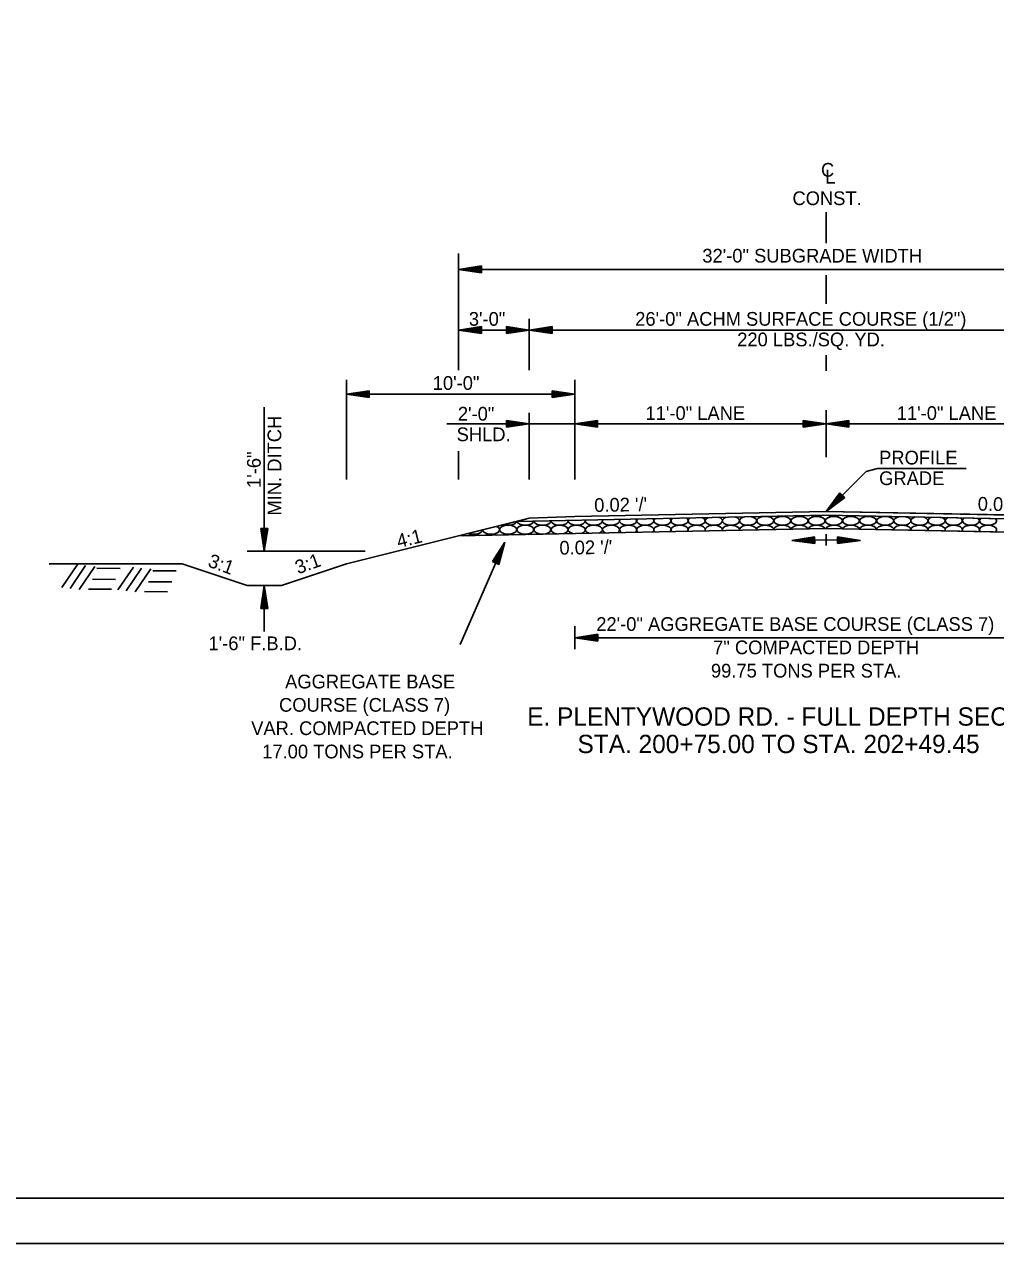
# Model space of a CAD drawing. Extents: x 1371763 to 1372860, y 385599 to 385872.
# Drawn here: x 1372733.4 to 1372775.9, y 385598.6 to 385651.9 of the extents above; entities that cross this region are included whole.
import ezdxf

# ---------------------------------------------------------------- set-up
doc = ezdxf.new("R2010")
doc.units = 0
for name, color, linetype in [('R_Border', 7, 'Continuous'), ('R_Draft', 7, 'Continuous'), ('R_Fin Surface', 7, 'Continuous'), ('R_No Plot', 7, 'Continuous')]:
    doc.layers.add(name, color=color, linetype=linetype)

msp = doc.modelspace()

# ---------------------------------------------------------------- linework, layer by layer
at = {"layer": 'R_Border'}
msp.add_line((1372857.298, 385600.577), (1372699.208, 385600.577), dxfattribs=at)
at = {"layer": 'R_Draft'}
for p, q in [((1372768.462, 385642.351), (1372768.462, 385643.701)), ((1372752.376, 385636.792), (1372752.376, 385641.892)), ((1372753.376, 385641.351), (1372752.376, 385641.201)), ((1372753.376, 385641.326), (1372752.543, 385641.201)), ((1372753.376, 385641.351), (1372753.376, 385641.051)), ((1372752.376, 385641.201), (1372784.541, 385641.201)), ((1372753.376, 385641.051), (1372752.376, 385641.201)), ((1372753.376, 385641.076), (1372752.543, 385641.201)), ((1372753.376, 385641.301), (1372752.715, 385641.201)), ((1372753.376, 385641.102), (1372752.715, 385641.201)), ((1372753.376, 385641.276), (1372752.882, 385641.201)), ((1372753.376, 385641.127), (1372752.882, 385641.201)), ((1372753.376, 385641.25), (1372753.051, 385641.201)), ((1372753.376, 385641.152), (1372753.051, 385641.201)), ((1372753.376, 385641.225), (1372753.218, 385641.201)), ((1372753.376, 385641.178), (1372753.218, 385641.201)), ((1372768.462, 385639.701), (1372768.462, 385640.951)), ((1372753.376, 385638.699), (1372752.376, 385638.549)), ((1372753.376, 385638.674), (1372752.543, 385638.549)), ((1372753.376, 385638.649), (1372752.715, 385638.549)), ((1372753.376, 385638.399), (1372753.376, 385638.699)), ((1372754.463, 385638.699), (1372755.463, 385638.549)), ((1372754.463, 385638.399), (1372754.463, 385638.699)), ((1372754.463, 385638.674), (1372755.296, 385638.549)), ((1372754.463, 385638.649), (1372755.124, 385638.549)), ((1372755.463, 385636.792), (1372755.463, 385639.037)), ((1372756.463, 385638.699), (1372755.463, 385638.549)), ((1372756.463, 385638.674), (1372755.63, 385638.549)), ((1372756.463, 385638.649), (1372755.802, 385638.549)), ((1372756.463, 385638.699), (1372756.463, 385638.399)), ((1372753.376, 385638.399), (1372752.376, 385638.549)), ((1372752.376, 385638.549), (1372755.463, 385638.549)), ((1372753.376, 385638.424), (1372752.543, 385638.549)), ((1372753.376, 385638.45), (1372752.715, 385638.549)), ((1372753.376, 385638.624), (1372752.882, 385638.549)), ((1372753.376, 385638.475), (1372752.882, 385638.549)), ((1372753.376, 385638.598), (1372753.051, 385638.549)), ((1372753.376, 385638.501), (1372753.051, 385638.549)), ((1372753.376, 385638.573), (1372753.218, 385638.549)), ((1372753.376, 385638.526), (1372753.218, 385638.549)), ((1372754.463, 385638.624), (1372754.958, 385638.549)), ((1372754.463, 385638.598), (1372754.788, 385638.549)), ((1372754.463, 385638.573), (1372754.621, 385638.549)), ((1372754.463, 385638.399), (1372755.463, 385638.549)), ((1372754.463, 385638.501), (1372754.788, 385638.549)), ((1372754.463, 385638.45), (1372755.124, 385638.549)), ((1372754.463, 385638.424), (1372755.296, 385638.549)), ((1372754.463, 385638.475), (1372754.958, 385638.549)), ((1372754.463, 385638.526), (1372754.621, 385638.549)), ((1372756.463, 385638.399), (1372755.463, 385638.549)), ((1372755.463, 385638.549), (1372781.46, 385638.549)), ((1372756.463, 385638.424), (1372755.63, 385638.549)), ((1372756.463, 385638.45), (1372755.802, 385638.549)), ((1372756.463, 385638.624), (1372755.969, 385638.549)), ((1372756.463, 385638.475), (1372755.969, 385638.549)), ((1372756.463, 385638.598), (1372756.138, 385638.549)), ((1372756.463, 385638.5), (1372756.138, 385638.549)), ((1372756.463, 385638.573), (1372756.305, 385638.549)), ((1372756.463, 385638.526), (1372756.305, 385638.549)), ((1372768.458, 385636.764), (1372768.458, 385637.449)), ((1372747.462, 385632.006), (1372747.462, 385636.371)), ((1372757.462, 385632.006), (1372757.462, 385636.371)), ((1372748.462, 385635.896), (1372747.462, 385635.746)), ((1372748.462, 385635.596), (1372747.462, 385635.746)), ((1372747.462, 385635.746), (1372757.462, 385635.746)), ((1372748.462, 385635.871), (1372747.629, 385635.746)), ((1372748.462, 385635.621), (1372747.629, 385635.746)), ((1372748.462, 385635.846), (1372747.801, 385635.746)), ((1372748.462, 385635.647), (1372747.801, 385635.746)), ((1372748.462, 385635.821), (1372747.967, 385635.746)), ((1372748.462, 385635.672), (1372747.967, 385635.746)), ((1372748.462, 385635.795), (1372748.137, 385635.746)), ((1372748.462, 385635.698), (1372748.137, 385635.746)), ((1372748.462, 385635.77), (1372748.304, 385635.746)), ((1372748.462, 385635.723), (1372748.304, 385635.746)), ((1372748.462, 385635.596), (1372748.462, 385635.896)), ((1372756.462, 385635.896), (1372757.462, 385635.746)), ((1372756.462, 385635.596), (1372756.462, 385635.896)), ((1372756.462, 385635.871), (1372757.295, 385635.746)), ((1372756.462, 385635.846), (1372757.123, 385635.746)), ((1372756.462, 385635.821), (1372756.956, 385635.746)), ((1372756.462, 385635.795), (1372756.787, 385635.746)), ((1372756.462, 385635.77), (1372756.62, 385635.746)), ((1372756.462, 385635.596), (1372757.462, 385635.746)), ((1372756.462, 385635.698), (1372756.787, 385635.746)), ((1372756.462, 385635.647), (1372757.123, 385635.746)), ((1372756.462, 385635.621), (1372757.295, 385635.746)), ((1372756.462, 385635.672), (1372756.956, 385635.746)), ((1372756.462, 385635.723), (1372756.62, 385635.746)), ((1372743.867, 385628.871), (1372743.867, 385635.169)), ((1372755.463, 385632.006), (1372755.463, 385634.933)), ((1372768.458, 385632.991), (1372768.458, 385635.045)), ((1372751.858, 385634.445), (1372768.458, 385634.445)), ((1372754.463, 385634.595), (1372755.463, 385634.445)), ((1372754.463, 385634.295), (1372754.463, 385634.595)), ((1372754.463, 385634.57), (1372755.296, 385634.445)), ((1372754.463, 385634.544), (1372755.124, 385634.445)), ((1372754.463, 385634.519), (1372754.958, 385634.445)), ((1372754.463, 385634.494), (1372754.788, 385634.445)), ((1372754.463, 385634.468), (1372754.621, 385634.445)), ((1372754.463, 385634.295), (1372755.463, 385634.445)), ((1372754.463, 385634.396), (1372754.788, 385634.445)), ((1372754.463, 385634.345), (1372755.124, 385634.445)), ((1372754.463, 385634.32), (1372755.296, 385634.445)), ((1372754.463, 385634.37), (1372754.958, 385634.445)), ((1372754.463, 385634.421), (1372754.621, 385634.445)), ((1372758.458, 385634.595), (1372757.458, 385634.445)), ((1372758.458, 385634.295), (1372757.458, 385634.445)), ((1372758.458, 385634.57), (1372757.625, 385634.445)), ((1372758.458, 385634.32), (1372757.625, 385634.445)), ((1372758.458, 385634.544), (1372757.797, 385634.445)), ((1372758.458, 385634.345), (1372757.797, 385634.445)), ((1372758.458, 385634.519), (1372757.964, 385634.445)), ((1372758.458, 385634.37), (1372757.964, 385634.445)), ((1372758.458, 385634.494), (1372758.133, 385634.445)), ((1372758.458, 385634.396), (1372758.133, 385634.445)), ((1372758.458, 385634.468), (1372758.3, 385634.445)), ((1372758.458, 385634.421), (1372758.3, 385634.445)), ((1372758.458, 385634.295), (1372758.458, 385634.595)), ((1372767.458, 385634.595), (1372768.458, 385634.445)), ((1372767.458, 385634.295), (1372767.458, 385634.595)), ((1372767.458, 385634.57), (1372768.291, 385634.445)), ((1372767.458, 385634.544), (1372768.119, 385634.445)), ((1372767.458, 385634.519), (1372767.953, 385634.445)), ((1372767.458, 385634.494), (1372767.783, 385634.445)), ((1372767.458, 385634.468), (1372767.616, 385634.445)), ((1372767.458, 385634.295), (1372768.458, 385634.445)), ((1372767.458, 385634.396), (1372767.783, 385634.445)), ((1372767.458, 385634.345), (1372768.119, 385634.445)), ((1372767.458, 385634.32), (1372768.291, 385634.445)), ((1372767.458, 385634.37), (1372767.953, 385634.445)), ((1372767.458, 385634.421), (1372767.616, 385634.445)), ((1372769.458, 385634.595), (1372768.458, 385634.445)), ((1372769.458, 385634.295), (1372768.458, 385634.445)), ((1372768.458, 385634.445), (1372786.722, 385634.445)), ((1372769.458, 385634.57), (1372768.625, 385634.445)), ((1372769.458, 385634.32), (1372768.625, 385634.445)), ((1372769.458, 385634.544), (1372768.797, 385634.445)), ((1372769.458, 385634.345), (1372768.797, 385634.445)), ((1372769.458, 385634.519), (1372768.964, 385634.445)), ((1372769.458, 385634.37), (1372768.964, 385634.445)), ((1372769.458, 385634.494), (1372769.133, 385634.445)), ((1372769.458, 385634.396), (1372769.133, 385634.445)), ((1372769.458, 385634.468), (1372769.3, 385634.445)), ((1372769.458, 385634.421), (1372769.3, 385634.445)), ((1372769.458, 385634.295), (1372769.458, 385634.595)), ((1372752.376, 385632.006), (1372752.376, 385633.256)), ((1372768.462, 385630.618), (1372770.212, 385632.368)), ((1372770.212, 385632.368), (1372770.712, 385632.493)), ((1372770.712, 385632.493), (1372774.597, 385632.493)), ((1372769.063, 385631.431), (1372768.462, 385630.618)), ((1372769.275, 385631.219), (1372768.462, 385630.618)), ((1372769.081, 385631.413), (1372768.58, 385630.736)), ((1372769.257, 385631.236), (1372768.58, 385630.736)), ((1372769.099, 385631.395), (1372768.702, 385630.857)), ((1372769.239, 385631.255), (1372768.702, 385630.857)), ((1372769.116, 385631.378), (1372768.819, 385630.975)), ((1372769.222, 385631.272), (1372768.819, 385630.975)), ((1372769.134, 385631.36), (1372768.939, 385631.095)), ((1372769.203, 385631.291), (1372768.939, 385631.095)), ((1372769.152, 385631.341), (1372769.057, 385631.213)), ((1372769.186, 385631.308), (1372769.057, 385631.213)), ((1372769.275, 385631.219), (1372769.063, 385631.431)), ((1372755.463, 385630.318), (1372747.463, 385628.318)), ((1372768.462, 385630.451), (1372754.912, 385630.18)), ((1372754.912, 385630.18), (1372768.462, 385630.451)), ((1372757.462, 385630.398), (1372755.463, 385630.318)), ((1372768.462, 385630.618), (1372757.462, 385630.398)), ((1372768.462, 385630.618), (1372757.462, 385630.398)), ((1372768.462, 385630.618), (1372779.462, 385630.398)), ((1372768.462, 385630.451), (1372782.011, 385630.18)), ((1372743.717, 385629.871), (1372743.867, 385628.871)), ((1372744.017, 385629.871), (1372743.717, 385629.871)), ((1372743.742, 385629.871), (1372743.867, 385629.038)), ((1372743.768, 385629.871), (1372743.867, 385629.21)), ((1372743.793, 385629.871), (1372743.867, 385629.376)), ((1372743.818, 385629.871), (1372743.867, 385629.546)), ((1372743.844, 385629.871), (1372743.867, 385629.713)), ((1372744.017, 385629.871), (1372743.867, 385628.871)), ((1372743.916, 385629.871), (1372743.867, 385629.546)), ((1372743.967, 385629.871), (1372743.867, 385629.21)), ((1372743.992, 385629.871), (1372743.867, 385629.038)), ((1372743.942, 385629.871), (1372743.867, 385629.376)), ((1372743.891, 385629.871), (1372743.867, 385629.713)), ((1372768.462, 385629.868), (1372752.376, 385629.546)), ((1372768.462, 385629.868), (1372784.547, 385629.546)), ((1372768.462, 385629.118), (1372768.462, 385629.618)), ((1372754.401, 385629.274), (1372752.435, 385624.797)), ((1372753.862, 385628.419), (1372754.401, 385629.274)), ((1372753.885, 385628.409), (1372754.334, 385629.121)), ((1372754.113, 385628.308), (1372754.334, 385629.121)), ((1372754.136, 385628.298), (1372754.401, 385629.274)), ((1372767.959, 385629.508), (1372766.962, 385629.338)), ((1372766.962, 385629.338), (1372768.462, 385629.368)), ((1372767.965, 385629.208), (1372766.962, 385629.338)), ((1372767.959, 385629.483), (1372767.129, 385629.341)), ((1372767.964, 385629.233), (1372767.129, 385629.341)), ((1372767.96, 385629.457), (1372767.301, 385629.345)), ((1372767.964, 385629.258), (1372767.301, 385629.345)), ((1372767.96, 385629.432), (1372767.468, 385629.348)), ((1372767.963, 385629.283), (1372767.468, 385629.348)), ((1372767.961, 385629.407), (1372767.637, 385629.351)), ((1372767.963, 385629.309), (1372767.637, 385629.351)), ((1372767.961, 385629.381), (1372767.804, 385629.355)), ((1372767.962, 385629.334), (1372767.804, 385629.355)), ((1372767.965, 385629.208), (1372767.959, 385629.508)), ((1372769.962, 385629.338), (1372768.462, 385629.368)), ((1372768.959, 385629.208), (1372768.965, 385629.508)), ((1372768.959, 385629.233), (1372769.795, 385629.341)), ((1372768.959, 385629.208), (1372769.962, 385629.338)), ((1372768.96, 385629.283), (1372769.456, 385629.348)), ((1372768.96, 385629.258), (1372769.623, 385629.345)), ((1372768.961, 385629.334), (1372769.12, 385629.355)), ((1372768.961, 385629.309), (1372769.287, 385629.351)), ((1372768.962, 385629.381), (1372769.12, 385629.355)), ((1372768.963, 385629.432), (1372769.456, 385629.348)), ((1372768.963, 385629.407), (1372769.287, 385629.351)), ((1372768.964, 385629.483), (1372769.795, 385629.341)), ((1372768.964, 385629.457), (1372769.623, 385629.345)), ((1372768.965, 385629.508), (1372769.962, 385629.338)), ((1372743.117, 385628.871), (1372748.277, 385628.871)), ((1372753.908, 385628.398), (1372754.265, 385628.964)), ((1372753.931, 385628.388), (1372754.198, 385628.811)), ((1372753.954, 385628.378), (1372754.13, 385628.656)), ((1372754.043, 385628.339), (1372754.13, 385628.656)), ((1372754.067, 385628.329), (1372754.198, 385628.811)), ((1372754.09, 385628.318), (1372754.265, 385628.964)), ((1372735.007, 385627.287), (1372735.683, 385628.288)), ((1372735.366, 385627.245), (1372736.042, 385628.247)), ((1372735.766, 385627.203), (1372736.442, 385628.205)), ((1372736.542, 385628.13), (1372737.56, 385628.121)), ((1372737.46, 385627.178), (1372738.136, 385628.18)), ((1372737.819, 385627.137), (1372738.494, 385628.138)), ((1372738.219, 385627.095), (1372738.895, 385628.096)), ((1372738.995, 385628.021), (1372740.013, 385628.013)), ((1372754.136, 385628.298), (1372753.862, 385628.419)), ((1372753.977, 385628.368), (1372754.063, 385628.503)), ((1372754.021, 385628.349), (1372754.063, 385628.503)), ((1372736.342, 385627.646), (1372737.36, 385627.637)), ((1372738.795, 385627.537), (1372739.813, 385627.529)), ((1372736.167, 385627.22), (1372737.185, 385627.212)), ((1372738.619, 385627.112), (1372739.637, 385627.103)), ((1372744.617, 385627.369), (1372743.117, 385627.369)), ((1372743.717, 385626.369), (1372743.867, 385627.369)), ((1372743.742, 385626.369), (1372743.867, 385627.202)), ((1372743.768, 385626.369), (1372743.867, 385627.03)), ((1372744.017, 385626.369), (1372743.867, 385627.369)), ((1372743.867, 385625.369), (1372743.867, 385627.369)), ((1372743.992, 385626.369), (1372743.867, 385627.202)), ((1372743.967, 385626.369), (1372743.867, 385627.03)), ((1372743.793, 385626.369), (1372743.867, 385626.864)), ((1372743.819, 385626.369), (1372743.867, 385626.694)), ((1372743.844, 385626.369), (1372743.867, 385626.527)), ((1372743.942, 385626.369), (1372743.867, 385626.864)), ((1372743.916, 385626.369), (1372743.867, 385626.694)), ((1372743.891, 385626.369), (1372743.867, 385626.527)), ((1372743.717, 385626.369), (1372744.017, 385626.369)), ((1372757.462, 385624.592), (1372757.462, 385625.592)), ((1372758.462, 385625.242), (1372757.462, 385625.092)), ((1372758.462, 385624.942), (1372757.462, 385625.092)), ((1372757.462, 385625.092), (1372779.462, 385625.092)), ((1372758.462, 385625.217), (1372757.629, 385625.092)), ((1372758.462, 385624.967), (1372757.629, 385625.092)), ((1372758.462, 385625.191), (1372757.801, 385625.092)), ((1372758.462, 385624.992), (1372757.801, 385625.092)), ((1372758.462, 385625.166), (1372757.967, 385625.092)), ((1372758.462, 385625.017), (1372757.967, 385625.092)), ((1372758.462, 385625.14), (1372758.137, 385625.092)), ((1372758.462, 385625.043), (1372758.137, 385625.092)), ((1372758.462, 385625.115), (1372758.304, 385625.092)), ((1372758.462, 385625.068), (1372758.304, 385625.092)), ((1372758.462, 385625.242), (1372758.462, 385624.942))]:
    msp.add_line(p, q, dxfattribs=at)
for points in [[(1372754.912, 385630.18), (1372752.376, 385629.546), (1372768.462, 385629.868), (1372784.547, 385629.546), (1372782.011, 385630.18), (1372768.462, 385630.451)], [(1372754.912, 385630.18), (1372755.463, 385630.318), (1372757.462, 385630.398), (1372768.462, 385630.618), (1372779.462, 385630.398), (1372781.46, 385630.318), (1372782.011, 385630.18), (1372768.462, 385630.451)]]:
    msp.add_lwpolyline(points, close=True, dxfattribs=at)
for points in [[(1372757.462, 385630.398), (1372755.463, 385630.318), (1372754.912, 385630.18)], [(1372768.462, 385630.451), (1372782.011, 385630.18), (1372781.46, 385630.318), (1372779.462, 385630.398), (1372768.462, 385630.618)]]:
    msp.add_lwpolyline(points, dxfattribs=at)
for centre, start_param, end_param in [((1372754.543, 385630.204), 4.15835, 6.162011), ((1372755.293, 385630.204), 3.26162, 6.240356), ((1372756.043, 385630.204), 3.184351, 6.317625), ((1372756.793, 385630.204), 3.107107, 6.394869), ((1372757.544, 385630.204), 3.029422, 6.472554), ((1372758.294, 385630.204), 2.950808, 6.551169), ((1372759.044, 385630.204), 2.870719, 6.631258), ((1372759.794, 385630.204), 2.788518, 6.713458), ((1372760.545, 385630.204), 2.703418, 6.798558), ((1372761.295, 385630.204), 2.614389, 6.887588), ((1372762.045, 385630.204), 2.519994, 6.981982), ((1372762.795, 385630.204), 2.418078, 7.083898), ((1372763.546, 385630.204), 2.305055, 7.196921), ((1372764.296, 385630.204), 2.173981, 7.327995), ((1372765.046, 385630.204), 2.007005, 7.494971), ((1372765.797, 385630.204), 1.650181, 7.851795), ((1372765.797, 385630.592), 4.714707, 4.787269), ((1372766.547, 385630.592), 4.353827, 5.148149), ((1372767.297, 385630.592), 4.186727, 5.31525), ((1372768.047, 385630.592), 4.055599, 5.446377), ((1372768.798, 385630.592), 3.965856, 5.381724), ((1372769.548, 385630.592), 4.094563, 5.253017), ((1372770.298, 385630.592), 4.256191, 5.091389), ((1372771.048, 385630.592), 4.541362, 4.806218), ((1372771.799, 385630.204), 1.908344, 7.439236), ((1372772.549, 385630.204), 2.081463, 7.266116), ((1372773.299, 385630.204), 2.215124, 7.132455), ((1372774.05, 385630.204), 2.329625, 7.017955), ((1372774.8, 385630.204), 2.432503, 6.915077), ((1372775.55, 385630.204), 2.527568, 6.820012), ((1372752.292, 385629.426), 0.690409, 0.924088), ((1372753.042, 385629.426), 0.791564, 2.427227), ((1372753.042, 385629.815), 4.086186, 6.238062), ((1372753.792, 385629.815), 3.185753, 7.138496), ((1372753.792, 385629.426), 0.903428, 2.315363), ((1372754.543, 385629.426), 1.032506, 2.186285), ((1372755.293, 385629.426), 1.194956, 2.023835), ((1372756.043, 385629.426), 1.487019, 1.731772), ((1372756.793, 385629.815), 5.130596, 10.654565), ((1372757.544, 385629.815), 5.302696, 10.482466), ((1372758.294, 385629.815), 5.435936, 10.349225), ((1372759.044, 385629.815), 5.550199, 10.234963), ((1372759.794, 385629.815), 5.652922, 10.132239), ((1372760.545, 385629.815), 5.747881, 10.037281), ((1372761.295, 385629.815), 5.837319, 9.947843), ((1372762.045, 385629.815), 1.16015, 3.579256), ((1372762.045, 385629.815), 5.92272, 7.443336), ((1372762.795, 385629.815), 0.985808, 3.496834), ((1372762.795, 385629.815), 6.005142, 7.268993), ((1372763.546, 385629.815), 0.851648, 3.416586), ((1372763.546, 385629.815), 6.085391, 7.134833), ((1372764.296, 385629.815), 0.736866, 3.337864), ((1372764.296, 385629.815), 6.164113, 7.020051), ((1372765.046, 385629.815), 0.633805, 3.260117), ((1372765.046, 385629.815), 6.241859, 6.916991), ((1372765.797, 385629.815), 0.035938, 3.182853), ((1372766.547, 385629.815), 0.113186, 3.105605), ((1372767.297, 385629.815), 0.190884, 3.027907), ((1372768.047, 385629.815), 0.269522, 2.949269), ((1372768.798, 385629.815), 0.20065, 2.869145), ((1372769.548, 385629.815), 0.121883, 2.942511), ((1372770.298, 385629.815), 0.044111, 3.020284), ((1372771.048, 385629.815), 0.606178, 3.097557), ((1372771.048, 385629.815), 6.250023, 6.889363), ((1372771.799, 385629.815), 0.700695, 3.174798), ((1372771.799, 385629.815), 6.172782, 6.98388), ((1372772.549, 385629.815), 0.802786, 3.252471), ((1372772.549, 385629.815), 6.095109, 7.085972), ((1372773.299, 385629.815), 0.916077, 3.331066), ((1372773.299, 385629.815), 6.016513, 7.199262), ((1372774.05, 385629.815), 1.047616, 3.411126), ((1372774.05, 385629.815), 5.936454, 7.330801), ((1372774.8, 385629.815), 1.215673, 3.493286), ((1372774.8, 385629.815), 5.854294, 7.498859), ((1372775.55, 385629.815), 5.769249, 9.861516)]:
    msp.add_ellipse(centre, major_axis=(0.375, 0), ratio=0.517889, start_param=start_param, end_param=end_param, dxfattribs=at)
for centre in [(1372766.547, 385630.204), (1372767.297, 385630.204), (1372768.047, 385630.204), (1372768.798, 385630.204), (1372769.548, 385630.204), (1372770.298, 385630.204), (1372771.048, 385630.204), (1372754.543, 385629.815), (1372755.293, 385629.815), (1372756.043, 385629.815)]:
    msp.add_ellipse(centre, major_axis=(0.375, 0), ratio=0.517889, dxfattribs=at)
at = {"layer": 'R_Fin Surface'}
for p, q in [((1372734.454, 385628.318), (1372740.271, 385628.318)), ((1372740.271, 385628.318), (1372743.117, 385627.369)), ((1372744.617, 385627.369), (1372747.463, 385628.318)), ((1372743.117, 385627.369), (1372744.617, 385627.369))]:
    msp.add_line(p, q, dxfattribs=at)
at = {"layer": 'R_No Plot'}
msp.add_line((1372693.007, 385598.587), (1372859.674, 385598.587), dxfattribs=at)
for points in [[(1372693.004, 385705.254), (1372859.674, 385705.254), (1372859.674, 385598.585), (1372693.004, 385598.585)], [(1372816.168, 385703.307), (1372825.978, 385703.307), (1372825.978, 385698.367), (1372834.034, 385698.367), (1372845.634, 385698.367), (1372845.634, 385682.032), (1372857.238, 385682.032), (1372857.298, 385600.577), (1372699.208, 385600.577), (1372699.208, 385703.307)]]:
    msp.add_lwpolyline(points, close=True, dxfattribs=at)

# ---------------------------------------------------------------- texts
at = {"layer": 'R_Draft'}
for s, rotation, p in [('C', 360, (1372768.237, 385645.258)), ('L', 360, (1372768.424, 385644.958)), ('CONST.', 360, (1372766.988, 385644.014)), ('32\'-0" SUBGRADE WIDTH', 360, (1372763.043, 385641.501)), ('3\'-0"', 360, (1372752.821, 385638.736)), ('26\'-0" ACHM SURFACE COURSE (1/2")', 360, (1372760.104, 385638.737)), ('220 LBS./SQ. YD.', 360, (1372764.569, 385637.837)), ('10\'-0"', 360, (1372751.241, 385635.933)), ('2\'-0"', 0, (1372752.341, 385634.587)), ('11\'-0" LANE', 360, (1372760.554, 385634.616)), ('11\'-0" LANE', 360, (1372771.554, 385634.616)), ('MIN. DITCH', 90, (1372744.611, 385630.433)), ('SHLD.', 0, (1372752.287, 385633.687)), ('1\'-6"', 90, (1372743.711, 385631.64)), ("0.02 '/'", 0.9853, (1372758.315, 385630.589)), ("0.02 '/'", 359.0147, (1372775.094, 385630.65)), ('4:1', 14.0362, (1372749.745, 385629.006)), ("0.02 '/'", 0.9853, (1372756.792, 385628.721)), ('3:1', 340.0022, (1372741.36, 385628.216)), ('3:1', 19.9978, (1372745.348, 385627.859)), ('22\'-0" AGGREGATE BASE COURSE (CLASS 7)', 360, (1372758.399, 385625.388)), ('1\'-6" F.B.D.', 360, (1372741.425, 385624.544)), ('7" COMPACTED DEPTH', 360, (1372763.515, 385624.368)), (' 99.75 TONS PER STA.', 360, (1372763.197, 385623.348)), ('AGGREGATE BASE ', 0, (1372744.778, 385622.872)), ('COURSE (CLASS 7)', 0, (1372744.513, 385621.852)), ('VAR. COMPACTED DEPTH', 0, (1372743.294, 385620.832)), ('17.00 TONS PER STA.', 0, (1372743.776, 385619.812))]:
    msp.add_text(s, height=0.6, rotation=rotation, dxfattribs=at).set_placement(p)
for s, height, p in [('PROFILE', 0.6, (1372770.782, 385632.668)), ('GRADE', 0.6, (1372770.782, 385631.768)), ('E. PLENTYWOOD RD. - FULL DEPTH SECTION', 0.8, (1372755.375, 385621.243)), ('STA. 200+75.00 TO STA. 202+49.45', 0.8, (1372757.577, 385620.043))]:
    msp.add_text(s, height=height, dxfattribs=at).set_placement(p)

doc.saveas('drawing.dxf')
